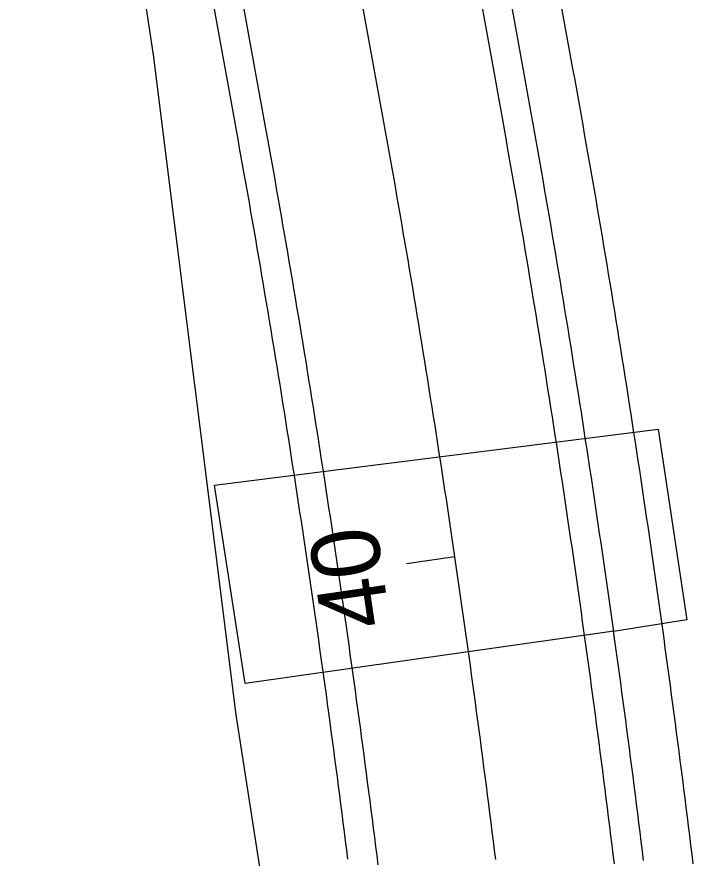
# Model space of a CAD drawing. Extents: x 2318076 to 2324211, y 613525 to 629939.
# Drawn here: x 2318877.4 to 2318946.6, y 618903.5 to 618989.5 of the extents above; entities that cross this region are included whole.
import ezdxf

# ---------------------------------------------------------------- set-up
doc = ezdxf.new("R2010")
doc.units = 0
for name, color, linetype in [('BR_X_Slab_Object', 7, 'Continuous'), ('GE_P_CL_50', 7, 'Continuous'), ('PV_P_EOP', 7, 'Continuous'), ('PV_P_Shoulder', 7, 'Continuous'), ('RD_X_GR_Lt', 7, 'Continuous'), ('RD_X_GR_Rt', 7, 'Continuous')]:
    doc.layers.add(name, color=color, linetype=linetype)

msp = doc.modelspace()

# ---------------------------------------------------------------- linework, layer by layer
at = {"layer": 'BR_X_Slab_Object'}
msp.add_lwpolyline([(2318938.52, 618926.67), (2318900.802, 618921.312), (2318897.659, 618941.601), (2318943.052, 618947.32), (2318945.992, 618927.813), (2318945.992, 618927.813), (2318938.492, 618926.645)], dxfattribs=at)
at = {"layer": 'GE_P_CL_50'}
msp.add_line((2318922.252, 618934.263), (2318917.304, 618933.539), dxfattribs=at)
msp.add_lwpolyline([(2318926.425, 618903.306), (2318926.308, 618904.253), (2318926.191, 618905.199), (2318926.073, 618906.145), (2318925.954, 618907.091), (2318925.834, 618908.037), (2318925.714, 618908.983), (2318925.593, 618909.928), (2318925.471, 618910.874), (2318925.349, 618911.82), (2318925.226, 618912.765), (2318925.103, 618913.711), (2318924.979, 618914.656), (2318924.854, 618915.601), (2318924.728, 618916.547), (2318924.602, 618917.492), (2318924.475, 618918.437), (2318924.348, 618919.382), (2318924.22, 618920.327), (2318924.091, 618921.271), (2318923.961, 618922.216), (2318923.831, 618923.161), (2318923.7, 618924.105), (2318923.569, 618925.049), (2318923.437, 618925.994), (2318923.304, 618926.938), (2318923.171, 618927.882), (2318923.037, 618928.826), (2318922.902, 618929.77), (2318922.767, 618930.714), (2318922.631, 618931.658), (2318922.494, 618932.601), (2318922.357, 618933.545), (2318922.219, 618934.488), (2318922.08, 618935.432), (2318921.941, 618936.375), (2318921.801, 618937.318), (2318921.66, 618938.261), (2318921.519, 618939.204), (2318921.377, 618940.147), (2318921.234, 618941.09), (2318921.091, 618942.032), (2318920.947, 618942.975), (2318920.802, 618943.917), (2318920.657, 618944.86), (2318920.511, 618945.802), (2318920.365, 618946.744), (2318920.218, 618947.686), (2318920.07, 618948.628), (2318919.921, 618949.57), (2318919.772, 618950.512), (2318919.622, 618951.453), (2318919.472, 618952.395), (2318919.321, 618953.336), (2318919.169, 618954.277), (2318919.017, 618955.219), (2318918.864, 618956.16), (2318918.71, 618957.101), (2318918.555, 618958.041), (2318918.4, 618958.982), (2318918.245, 618959.923), (2318918.088, 618960.863), (2318917.931, 618961.804), (2318917.774, 618962.744), (2318917.615, 618963.684), (2318917.456, 618964.624), (2318917.297, 618965.564), (2318917.137, 618966.504), (2318916.976, 618967.444), (2318916.814, 618968.383), (2318916.652, 618969.323), (2318916.489, 618970.262), (2318916.325, 618971.201), (2318916.161, 618972.14), (2318915.996, 618973.079), (2318915.831, 618974.018), (2318915.665, 618974.957), (2318915.498, 618975.896), (2318915.33, 618976.834), (2318915.162, 618977.772), (2318914.994, 618978.711), (2318914.824, 618979.649), (2318914.654, 618980.587), (2318914.483, 618981.525), (2318914.312, 618982.462), (2318914.14, 618983.4), (2318905.176, 619032.789)], dxfattribs=at)
at = {"layer": 'PV_P_EOP'}
for points in [[(2318938.569, 618902.865), (2318938.453, 618903.819), (2318938.335, 618904.774), (2318938.217, 618905.729), (2318938.099, 618906.683), (2318937.979, 618907.637), (2318937.859, 618908.592), (2318937.739, 618909.546), (2318937.618, 618910.5), (2318937.496, 618911.454), (2318937.373, 618912.408), (2318937.25, 618913.362), (2318937.126, 618914.316), (2318937.001, 618915.27), (2318936.876, 618916.223), (2318936.75, 618917.177), (2318936.623, 618918.13), (2318936.496, 618919.084), (2318936.368, 618920.037), (2318936.239, 618920.99), (2318936.11, 618921.943), (2318935.98, 618922.896), (2318935.85, 618923.849), (2318935.718, 618924.802), (2318935.586, 618925.755), (2318935.454, 618926.708), (2318935.321, 618927.66), (2318935.187, 618928.613), (2318935.052, 618929.565), (2318934.917, 618930.517), (2318934.781, 618931.47), (2318934.644, 618932.422), (2318934.507, 618933.374), (2318934.369, 618934.326), (2318934.231, 618935.277), (2318934.092, 618936.229), (2318933.952, 618937.181), (2318933.811, 618938.132), (2318933.67, 618939.084), (2318933.528, 618940.035), (2318933.386, 618940.986), (2318933.242, 618941.937), (2318933.099, 618942.888), (2318932.954, 618943.839), (2318932.809, 618944.79), (2318932.663, 618945.741), (2318932.517, 618946.691), (2318932.369, 618947.642), (2318932.222, 618948.592), (2318932.073, 618949.543), (2318931.924, 618950.493), (2318931.774, 618951.443), (2318931.624, 618952.393), (2318931.473, 618953.343), (2318931.321, 618954.293), (2318931.168, 618955.242), (2318931.015, 618956.192), (2318930.862, 618957.141), (2318930.707, 618958.09), (2318930.552, 618959.04), (2318930.396, 618959.989), (2318930.24, 618960.938), (2318930.083, 618961.887), (2318929.925, 618962.835), (2318929.767, 618963.784), (2318929.608, 618964.732), (2318929.448, 618965.681), (2318929.288, 618966.629), (2318929.127, 618967.577), (2318928.965, 618968.525), (2318928.803, 618969.473), (2318928.64, 618970.421), (2318928.476, 618971.369), (2318928.312, 618972.316), (2318928.147, 618973.264), (2318927.981, 618974.211), (2318927.815, 618975.158), (2318927.648, 618976.106), (2318927.48, 618977.052), (2318927.312, 618977.999), (2318927.143, 618978.946), (2318926.974, 618979.893), (2318926.803, 618980.839), (2318926.632, 618981.785), (2318926.461, 618982.732), (2318926.289, 618983.678), (2318926.116, 618984.624), (2318925.945, 618985.554), (2318916.991, 619034.89)], [(2318914.4, 618902.777), (2318914.283, 618903.714), (2318914.166, 618904.652), (2318914.048, 618905.59), (2318913.929, 618906.528), (2318913.81, 618907.465), (2318913.69, 618908.403), (2318913.57, 618909.34), (2318913.449, 618910.277), (2318913.327, 618911.215), (2318913.204, 618912.152), (2318913.081, 618913.089), (2318912.958, 618914.026), (2318912.833, 618914.963), (2318912.708, 618915.9), (2318912.582, 618916.836), (2318912.456, 618917.773), (2318912.329, 618918.71), (2318912.201, 618919.646), (2318912.073, 618920.583), (2318911.944, 618921.519), (2318911.814, 618922.455), (2318911.684, 618923.391), (2318911.553, 618924.327), (2318911.422, 618925.263), (2318911.289, 618926.199), (2318911.157, 618927.135), (2318911.023, 618928.07), (2318910.889, 618929.006), (2318910.754, 618929.941), (2318910.618, 618930.877), (2318910.482, 618931.812), (2318910.346, 618932.747), (2318910.208, 618933.682), (2318910.07, 618934.617), (2318909.931, 618935.552), (2318909.792, 618936.487), (2318909.652, 618937.422), (2318909.511, 618938.356), (2318909.37, 618939.291), (2318909.228, 618940.225), (2318909.085, 618941.16), (2318908.942, 618942.094), (2318908.798, 618943.028), (2318908.653, 618943.962), (2318908.508, 618944.896), (2318908.362, 618945.83), (2318908.216, 618946.763), (2318908.068, 618947.697), (2318907.921, 618948.63), (2318907.772, 618949.564), (2318907.623, 618950.497), (2318907.473, 618951.43), (2318907.323, 618952.363), (2318907.172, 618953.296), (2318907.02, 618954.229), (2318906.868, 618955.162), (2318906.714, 618956.094), (2318906.561, 618957.027), (2318906.406, 618957.959), (2318906.251, 618958.891), (2318906.096, 618959.823), (2318905.94, 618960.756), (2318905.783, 618961.687), (2318905.625, 618962.619), (2318905.467, 618963.551), (2318905.308, 618964.483), (2318905.148, 618965.414), (2318904.988, 618966.345), (2318904.828, 618967.277), (2318904.666, 618968.208), (2318904.504, 618969.139), (2318904.341, 618970.07), (2318904.178, 618971), (2318904.014, 618971.931), (2318903.849, 618972.861), (2318903.684, 618973.792), (2318903.518, 618974.722), (2318903.351, 618975.652), (2318903.184, 618976.582), (2318903.016, 618977.512), (2318902.847, 618978.442), (2318902.678, 618979.372), (2318902.508, 618980.301), (2318902.335, 618981.246), (2318893.362, 619030.687)]]:
    msp.add_lwpolyline(points, dxfattribs=at)
at = {"layer": 'PV_P_Shoulder'}
for points in [[(2318941.547, 618903.228), (2318941.43, 618904.184), (2318941.313, 618905.141), (2318941.195, 618906.098), (2318941.076, 618907.054), (2318940.956, 618908.011), (2318940.836, 618908.967), (2318940.715, 618909.923), (2318940.593, 618910.88), (2318940.471, 618911.836), (2318940.348, 618912.792), (2318940.225, 618913.748), (2318940.101, 618914.704), (2318939.976, 618915.659), (2318939.85, 618916.615), (2318939.724, 618917.571), (2318939.597, 618918.526), (2318939.469, 618919.482), (2318939.341, 618920.437), (2318939.212, 618921.392), (2318939.083, 618922.348), (2318938.953, 618923.303), (2318938.822, 618924.258), (2318938.69, 618925.213), (2318938.558, 618926.167), (2318938.425, 618927.122), (2318938.292, 618928.077), (2318938.157, 618929.031), (2318938.023, 618929.986), (2318937.887, 618930.94), (2318937.751, 618931.894), (2318937.614, 618932.849), (2318937.476, 618933.803), (2318937.338, 618934.757), (2318937.199, 618935.711), (2318937.06, 618936.664), (2318936.92, 618937.618), (2318936.779, 618938.572), (2318936.637, 618939.525), (2318936.495, 618940.479), (2318936.352, 618941.432), (2318936.209, 618942.385), (2318936.065, 618943.338), (2318935.92, 618944.291), (2318935.774, 618945.244), (2318935.628, 618946.197), (2318935.481, 618947.149), (2318935.334, 618948.102), (2318935.186, 618949.054), (2318935.037, 618950.007), (2318934.888, 618950.959), (2318934.738, 618951.911), (2318934.587, 618952.863), (2318934.435, 618953.815), (2318934.283, 618954.767), (2318934.13, 618955.719), (2318933.977, 618956.67), (2318933.823, 618957.622), (2318933.668, 618958.573), (2318933.513, 618959.524), (2318933.357, 618960.476), (2318933.2, 618961.427), (2318933.042, 618962.377), (2318932.884, 618963.328), (2318932.726, 618964.279), (2318932.566, 618965.23), (2318932.406, 618966.18), (2318932.246, 618967.13), (2318932.084, 618968.081), (2318931.922, 618969.031), (2318931.759, 618969.981), (2318931.596, 618970.931), (2318931.432, 618971.88), (2318931.267, 618972.83), (2318931.102, 618973.78), (2318930.936, 618974.729), (2318930.769, 618975.678), (2318930.602, 618976.627), (2318930.434, 618977.576), (2318930.266, 618978.525), (2318930.096, 618979.474), (2318929.926, 618980.423), (2318929.756, 618981.371), (2318929.584, 618982.32), (2318929.413, 618983.268), (2318929.24, 618984.216), (2318929.067, 618985.164), (2318928.896, 618986.093), (2318919.944, 619035.416)], [(2318911.306, 618903.343), (2318911.189, 618904.279), (2318911.071, 618905.215), (2318910.953, 618906.15), (2318910.834, 618907.086), (2318910.715, 618908.021), (2318910.594, 618908.957), (2318910.474, 618909.892), (2318910.352, 618910.827), (2318910.23, 618911.762), (2318910.107, 618912.697), (2318909.984, 618913.632), (2318909.859, 618914.567), (2318909.735, 618915.502), (2318909.609, 618916.436), (2318909.483, 618917.371), (2318909.356, 618918.305), (2318909.229, 618919.24), (2318909.101, 618920.174), (2318908.972, 618921.108), (2318908.843, 618922.043), (2318908.713, 618922.977), (2318908.582, 618923.911), (2318908.451, 618924.844), (2318908.319, 618925.778), (2318908.186, 618926.712), (2318908.053, 618927.646), (2318907.919, 618928.579), (2318907.785, 618929.512), (2318907.65, 618930.446), (2318907.514, 618931.379), (2318907.377, 618932.312), (2318907.24, 618933.245), (2318907.102, 618934.178), (2318906.964, 618935.111), (2318906.825, 618936.044), (2318906.685, 618936.976), (2318906.545, 618937.909), (2318906.404, 618938.841), (2318906.262, 618939.774), (2318906.12, 618940.706), (2318905.977, 618941.638), (2318905.833, 618942.57), (2318905.689, 618943.502), (2318905.544, 618944.434), (2318905.398, 618945.365), (2318905.252, 618946.297), (2318905.105, 618947.229), (2318904.958, 618948.16), (2318904.81, 618949.091), (2318904.661, 618950.022), (2318904.511, 618950.954), (2318904.361, 618951.885), (2318904.21, 618952.815), (2318904.059, 618953.746), (2318903.907, 618954.677), (2318903.754, 618955.607), (2318903.601, 618956.538), (2318903.447, 618957.468), (2318903.292, 618958.398), (2318903.137, 618959.328), (2318902.981, 618960.258), (2318902.824, 618961.188), (2318902.667, 618962.118), (2318902.509, 618963.048), (2318902.351, 618963.977), (2318902.192, 618964.907), (2318902.032, 618965.836), (2318901.871, 618966.765), (2318901.71, 618967.694), (2318901.549, 618968.623), (2318901.386, 618969.552), (2318901.223, 618970.481), (2318901.059, 618971.409), (2318900.895, 618972.338), (2318900.73, 618973.266), (2318900.565, 618974.194), (2318900.398, 618975.122), (2318900.231, 618976.05), (2318900.064, 618976.978), (2318899.896, 618977.906), (2318899.727, 618978.833), (2318899.557, 618979.761), (2318899.384, 618980.707), (2318890.408, 619030.161)]]:
    msp.add_lwpolyline(points, dxfattribs=at)
at = {"layer": 'RD_X_GR_Lt'}
for p, q in [((2318891.417, 618985.607), (2318877.436, 619076.937)), ((2318899.884, 618918.122), (2318891.417, 618985.607)), ((2318914.324, 618824.85), (2318899.884, 618918.122))]:
    msp.add_line(p, q, dxfattribs=at)
at = {"layer": 'RD_X_GR_Rt'}
msp.add_lwpolyline([(2318946.627, 618902.872), (2318946.511, 618903.832), (2318946.393, 618904.792), (2318946.275, 618905.753), (2318946.157, 618906.713), (2318946.037, 618907.673), (2318945.917, 618908.633), (2318945.797, 618909.592), (2318945.675, 618910.552), (2318945.553, 618911.512), (2318945.431, 618912.471), (2318945.307, 618913.431), (2318945.183, 618914.39), (2318945.059, 618915.35), (2318944.933, 618916.309), (2318944.807, 618917.268), (2318944.681, 618918.227), (2318944.553, 618919.186), (2318944.425, 618920.145), (2318944.297, 618921.104), (2318944.167, 618922.063), (2318944.037, 618923.021), (2318943.907, 618923.98), (2318943.775, 618924.938), (2318943.643, 618925.897), (2318943.51, 618926.855), (2318943.377, 618927.813), (2318943.243, 618928.771), (2318943.108, 618929.729), (2318942.973, 618930.687), (2318942.837, 618931.645), (2318942.7, 618932.603), (2318942.563, 618933.56), (2318942.425, 618934.518), (2318942.286, 618935.475), (2318942.147, 618936.432), (2318942.007, 618937.39), (2318941.866, 618938.347), (2318941.725, 618939.304), (2318941.583, 618940.261), (2318941.44, 618941.218), (2318941.297, 618942.174), (2318941.153, 618943.131), (2318941.008, 618944.088), (2318940.863, 618945.044), (2318940.717, 618946), (2318940.57, 618946.957), (2318940.423, 618947.913), (2318940.275, 618948.869), (2318940.126, 618949.825), (2318939.977, 618950.78), (2318939.827, 618951.736), (2318939.676, 618952.692), (2318939.525, 618953.647), (2318939.373, 618954.602), (2318939.22, 618955.558), (2318939.067, 618956.513), (2318938.913, 618957.468), (2318938.758, 618958.423), (2318938.603, 618959.378), (2318938.447, 618960.332), (2318938.29, 618961.287), (2318938.133, 618962.241), (2318937.975, 618963.196), (2318937.816, 618964.15), (2318937.657, 618965.104), (2318937.497, 618966.058), (2318937.337, 618967.012), (2318937.175, 618967.966), (2318937.013, 618968.919), (2318936.851, 618969.873), (2318936.687, 618970.826), (2318936.524, 618971.78), (2318936.359, 618972.733), (2318936.194, 618973.686), (2318936.028, 618974.639), (2318935.861, 618975.592), (2318935.694, 618976.544), (2318935.526, 618977.497), (2318935.357, 618978.449), (2318935.188, 618979.402), (2318935.018, 618980.354), (2318934.848, 618981.306), (2318934.676, 618982.258), (2318934.505, 618983.21), (2318934.332, 618984.162), (2318934.159, 618985.113), (2318933.985, 618986.065), (2318933.815, 618986.99), (2318924.867, 619036.292)], dxfattribs=at)

# ---------------------------------------------------------------- texts
at = {"layer": 'GE_P_CL_50'}
msp.add_text('40', height=7, rotation=98.32169, dxfattribs=at).set_placement((2318915.676, 618927.397))

doc.saveas('drawing.dxf')
